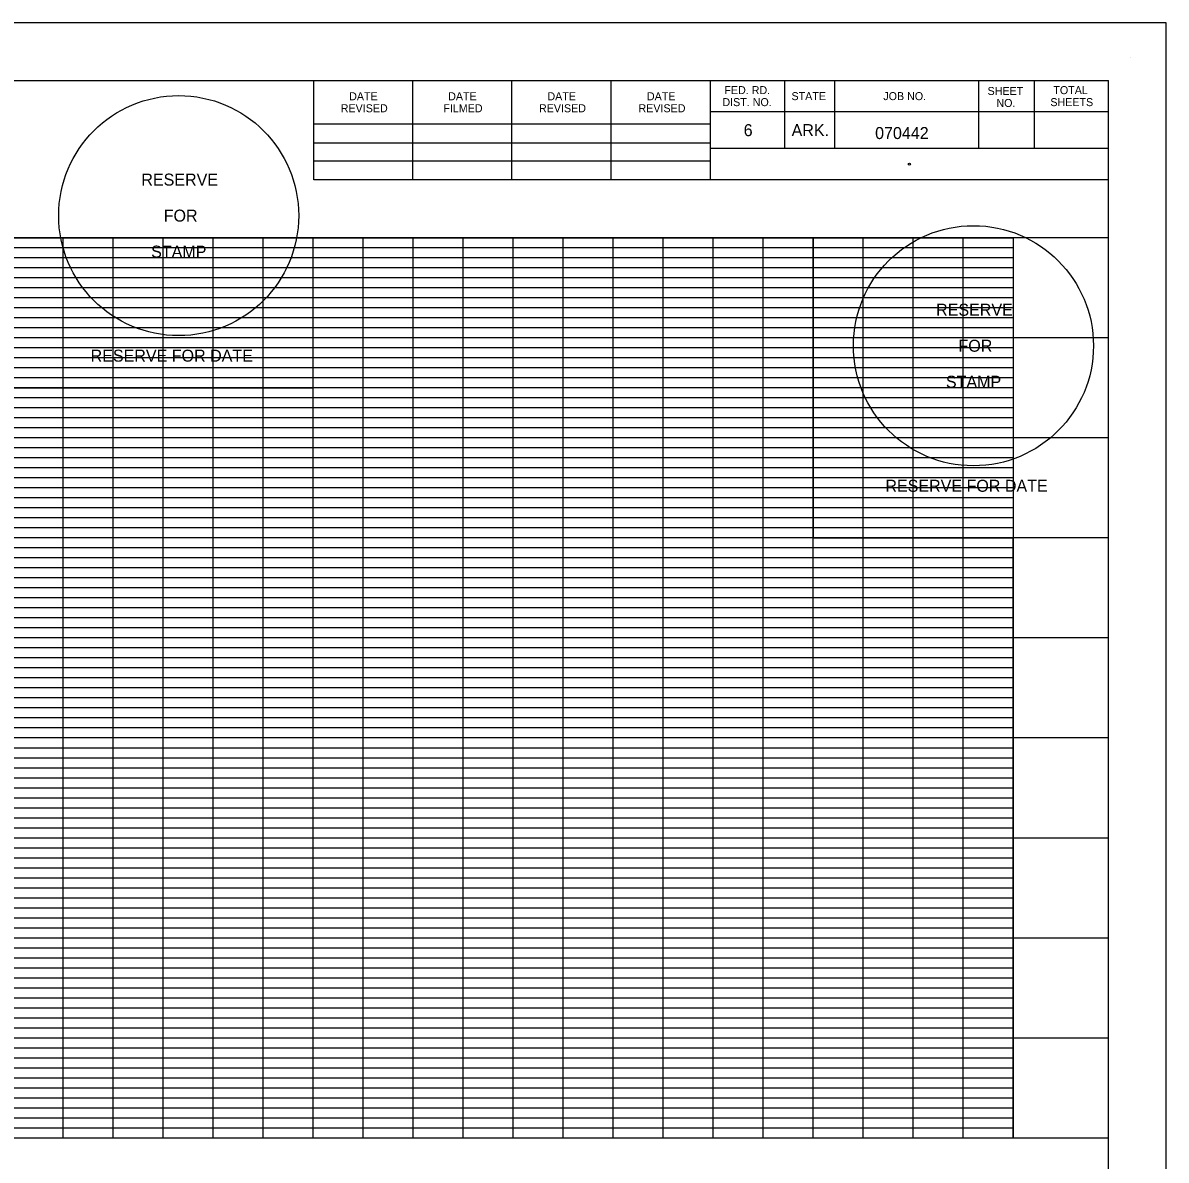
# Model space of a CAD drawing. Extents: x 1446988 to 1448688, y 2058337 to 2059437.
import ezdxf

# ---------------------------------------------------------------- set-up
doc = ezdxf.new("R2010")
doc.units = 0
for name, color, linetype in [('1', 7, 'Continuous'), ('G-ANNO-TEXT', 7, 'Continuous'), ('G-Border-Sheet', 7, 'Continuous'), ('G-Grid-Border-1', 7, 'Continuous'), ('G-Grid-Border-2', 7, 'Continuous'), ('G-Grid-Major-1', 7, 'Continuous'), ('G-Grid-Major-2', 7, 'Continuous'), ('G-Grid-Minor-1', 7, 'Continuous'), ('G-Grid-Minor-2', 7, 'Continuous'), ('G-No Plot-Anchor', 7, 'Continuous'), ('G-No Plot-Stamp-1', 7, 'Continuous'), ('G-No Plot-Stamp-2', 7, 'Continuous'), ('G-Table-Major', 7, 'Continuous'), ('G-Table-Minor', 7, 'Continuous')]:
    doc.layers.add(name, color=color, linetype=linetype)

msp = doc.modelspace()

# ---------------------------------------------------------------- linework, layer by layer
at = {"layer": '1'}
msp.add_lwpolyline([(1448688.42, 2059436.53), (1446988.42, 2059436.53), (1446988.42, 2058336.53), (1448688.42, 2058336.53)], close=True, dxfattribs=at)
at = {"layer": 'G-ANNO-TEXT'}
msp.add_line((1448670.52, 2059419.23), (1448670.52, 2059419.23), dxfattribs=at)
at = {"layer": 'G-Border-Sheet'}
for p in [(1447064.22, 2059407.69), (1448659.58, 2058365.37)]:
    msp.add_line(p, (1448659.58, 2059407.69), dxfattribs=at)
at = {"layer": 'G-Grid-Border-1'}
for p, q in [((1448508.75, 2059329.09), (1447064.22, 2059329.09)), ((1448659.58, 2058879.09), (1447064.22, 2058879.09))]:
    msp.add_line(p, q, dxfattribs=at)
msp.add_lwpolyline([(1447111.9, 2059329.09), (1448511.9, 2059329.09), (1448511.9, 2059179.09), (1448611.9, 2059179.09), (1448611.9, 2058879.09), (1447111.9, 2058879.09)], close=True, dxfattribs=at)
at = {"layer": 'G-Grid-Border-2'}
for p, q in [((1448261.9, 2059254.09), (1448261.9, 2059329.09)), ((1448659.58, 2059329.09), (1448261.9, 2059329.09)), ((1448261.9, 2059254.09), (1448261.9, 2059329.09)), ((1448111.9, 2059254.09), (1448261.9, 2059254.09)), ((1448111.9, 2059254.09), (1448261.9, 2059254.09)), ((1448611.9, 2058879.09), (1448611.9, 2059179.09)), ((1448659.58, 2058879.09), (1447064.22, 2058879.09))]:
    msp.add_line(p, q, dxfattribs=at)
msp.add_lwpolyline([(1447111.9, 2059329.09), (1448111.9, 2059329.09), (1448111.9, 2059254.09), (1448261.9, 2059254.09), (1448261.9, 2059329.09), (1448611.9, 2059329.09), (1448611.9, 2058879.09), (1447111.9, 2058879.09)], close=True, dxfattribs=at)
at = {"layer": 'G-Grid-Major-1'}
for p, q in [((1448161.9, 2058879.09), (1448161.9, 2059329.09)), ((1448211.9, 2058879.09), (1448211.9, 2059329.09)), ((1448261.9, 2058879.09), (1448261.9, 2059329.09)), ((1448311.9, 2058879.09), (1448311.9, 2059329.09)), ((1448361.9, 2058879.09), (1448361.9, 2059329.09)), ((1448411.9, 2058879.09), (1448411.9, 2059329.09)), ((1448461.9, 2058879.09), (1448461.9, 2059329.09)), ((1448511.9, 2058879.09), (1448511.9, 2059329.09)), ((1448511.9, 2059279.09), (1447064.22, 2059279.09)), ((1448511.9, 2059229.09), (1447064.22, 2059229.09)), ((1448659.58, 2059179.09), (1447064.22, 2059179.09)), ((1448561.9, 2058879.09), (1448561.9, 2059179.09)), ((1448659.58, 2059129.09), (1447064.22, 2059129.09)), ((1448659.58, 2059079.09), (1447064.22, 2059079.09)), ((1448659.58, 2059029.09), (1447064.22, 2059029.09)), ((1448659.58, 2058979.09), (1447064.22, 2058979.09)), ((1448659.58, 2058929.09), (1447064.22, 2058929.09))]:
    msp.add_line(p, q, dxfattribs=at)
at = {"layer": 'G-Grid-Major-2'}
for p, q in [((1448261.9, 2058879.09), (1448261.9, 2059329.09)), ((1448311.9, 2058879.09), (1448311.9, 2059329.09)), ((1448361.9, 2058879.09), (1448361.9, 2059329.09)), ((1448411.9, 2058879.09), (1448411.9, 2059329.09)), ((1448461.9, 2058879.09), (1448461.9, 2059329.09)), ((1448511.9, 2058879.09), (1448511.9, 2059329.09)), ((1448561.9, 2058879.09), (1448561.9, 2059329.09)), ((1448659.58, 2059279.09), (1448261.9, 2059279.09)), ((1448161.9, 2058879.09), (1448161.9, 2059254.09)), ((1448211.9, 2058879.09), (1448211.9, 2059254.09)), ((1448659.58, 2059229.09), (1447064.22, 2059229.09)), ((1448659.58, 2059179.09), (1447064.22, 2059179.09)), ((1448659.58, 2059129.09), (1447064.22, 2059129.09)), ((1448659.58, 2059079.09), (1447064.22, 2059079.09)), ((1448659.58, 2059029.09), (1447064.22, 2059029.09)), ((1448659.58, 2058979.09), (1447064.22, 2058979.09)), ((1448659.58, 2058929.09), (1447064.22, 2058929.09))]:
    msp.add_line(p, q, dxfattribs=at)
at = {"layer": 'G-Grid-Minor-1'}
for p, q in [((1448136.9, 2058879.09), (1448136.9, 2059329.09)), ((1448186.9, 2058879.09), (1448186.9, 2059329.09)), ((1448236.9, 2058879.09), (1448236.9, 2059329.09)), ((1448286.9, 2058879.09), (1448286.9, 2059329.09)), ((1448336.9, 2058879.09), (1448336.9, 2059329.09)), ((1448386.9, 2058879.09), (1448386.9, 2059329.09)), ((1448436.9, 2058879.09), (1448436.9, 2059329.09)), ((1448486.9, 2058879.09), (1448486.9, 2059329.09)), ((1448511.9, 2059324.09), (1447111.9, 2059324.09)), ((1448511.9, 2059319.09), (1447111.9, 2059319.09)), ((1448511.9, 2059314.09), (1447111.9, 2059314.09)), ((1448511.9, 2059309.09), (1447111.9, 2059309.09)), ((1448511.9, 2059304.09), (1447111.9, 2059304.09)), ((1448511.9, 2059299.09), (1447111.9, 2059299.09)), ((1448511.9, 2059294.09), (1447111.9, 2059294.09)), ((1448511.9, 2059289.09), (1447111.9, 2059289.09)), ((1448511.9, 2059284.09), (1447111.9, 2059284.09)), ((1448511.9, 2059274.09), (1447111.9, 2059274.09)), ((1448511.9, 2059269.09), (1447111.9, 2059269.09)), ((1448511.9, 2059264.09), (1447111.9, 2059264.09)), ((1448511.9, 2059259.09), (1447111.9, 2059259.09)), ((1448511.9, 2059254.09), (1447111.9, 2059254.09)), ((1448511.9, 2059249.09), (1447111.9, 2059249.09)), ((1448511.9, 2059244.09), (1447111.9, 2059244.09)), ((1448511.9, 2059239.09), (1447111.9, 2059239.09)), ((1448511.9, 2059234.09), (1447111.9, 2059234.09)), ((1448511.9, 2059224.09), (1447111.9, 2059224.09)), ((1448511.9, 2059219.09), (1447111.9, 2059219.09)), ((1448511.9, 2059214.09), (1447111.9, 2059214.09)), ((1448511.9, 2059209.09), (1447111.9, 2059209.09)), ((1448511.9, 2059204.09), (1447111.9, 2059204.09)), ((1448511.9, 2059199.09), (1447111.9, 2059199.09)), ((1448511.9, 2059194.09), (1447111.9, 2059194.09)), ((1448511.9, 2059189.09), (1447111.9, 2059189.09)), ((1448511.9, 2059184.09), (1447111.9, 2059184.09)), ((1448536.9, 2058879.09), (1448536.9, 2059179.09)), ((1448586.9, 2058879.09), (1448586.9, 2059179.09)), ((1448611.9, 2059174.09), (1447111.9, 2059174.09)), ((1448611.9, 2059169.09), (1447111.9, 2059169.09)), ((1448611.9, 2059164.09), (1447111.9, 2059164.09)), ((1448611.9, 2059159.09), (1447111.9, 2059159.09)), ((1448611.9, 2059154.09), (1447111.9, 2059154.09)), ((1448611.9, 2059149.09), (1447111.9, 2059149.09)), ((1448611.9, 2059144.09), (1447111.9, 2059144.09)), ((1448611.9, 2059139.09), (1447111.9, 2059139.09)), ((1448611.9, 2059134.09), (1447111.9, 2059134.09)), ((1448611.9, 2059124.09), (1447111.9, 2059124.09)), ((1448611.9, 2059119.09), (1447111.9, 2059119.09)), ((1448611.9, 2059114.09), (1447111.9, 2059114.09)), ((1448611.9, 2059109.09), (1447111.9, 2059109.09)), ((1448611.9, 2059104.09), (1447111.9, 2059104.09)), ((1448611.9, 2059099.09), (1447111.9, 2059099.09)), ((1448611.9, 2059094.09), (1447111.9, 2059094.09)), ((1448611.9, 2059089.09), (1447111.9, 2059089.09)), ((1448611.9, 2059084.09), (1447111.9, 2059084.09)), ((1448611.9, 2059074.09), (1447111.9, 2059074.09)), ((1448611.9, 2059069.09), (1447111.9, 2059069.09)), ((1448611.9, 2059064.09), (1447111.9, 2059064.09)), ((1448611.9, 2059059.09), (1447111.9, 2059059.09)), ((1448611.9, 2059054.09), (1447111.9, 2059054.09)), ((1448611.9, 2059049.09), (1447111.9, 2059049.09)), ((1448611.9, 2059044.09), (1447111.9, 2059044.09)), ((1448611.9, 2059039.09), (1447111.9, 2059039.09)), ((1448611.9, 2059034.09), (1447111.9, 2059034.09)), ((1448611.9, 2059024.09), (1447111.9, 2059024.09)), ((1448611.9, 2059019.09), (1447111.9, 2059019.09)), ((1448611.9, 2059014.09), (1447111.9, 2059014.09)), ((1448611.9, 2059009.09), (1447111.9, 2059009.09)), ((1448611.9, 2059004.09), (1447111.9, 2059004.09)), ((1448611.9, 2058999.09), (1447111.9, 2058999.09)), ((1448611.9, 2058994.09), (1447111.9, 2058994.09)), ((1448611.9, 2058989.09), (1447111.9, 2058989.09)), ((1448611.9, 2058984.09), (1447111.9, 2058984.09)), ((1448611.9, 2058974.09), (1447111.9, 2058974.09)), ((1448611.9, 2058969.09), (1447111.9, 2058969.09)), ((1448611.9, 2058964.09), (1447111.9, 2058964.09)), ((1448611.9, 2058959.09), (1447111.9, 2058959.09)), ((1448611.9, 2058954.09), (1447111.9, 2058954.09)), ((1448611.9, 2058949.09), (1447111.9, 2058949.09)), ((1448611.9, 2058944.09), (1447111.9, 2058944.09)), ((1448611.9, 2058939.09), (1447111.9, 2058939.09)), ((1448611.9, 2058934.09), (1447111.9, 2058934.09)), ((1448611.9, 2058924.09), (1447111.9, 2058924.09)), ((1448611.9, 2058919.09), (1447111.9, 2058919.09)), ((1448611.9, 2058914.09), (1447111.9, 2058914.09)), ((1448611.9, 2058909.09), (1447111.9, 2058909.09)), ((1448611.9, 2058904.09), (1447111.9, 2058904.09)), ((1448611.9, 2058899.09), (1447111.9, 2058899.09)), ((1448611.9, 2058894.09), (1447111.9, 2058894.09)), ((1448611.9, 2058889.09), (1447111.9, 2058889.09)), ((1448611.9, 2058884.09), (1447111.9, 2058884.09))]:
    msp.add_line(p, q, dxfattribs=at)
msp.add_lwpolyline([(1448611.9, 2059179.09), (1448611.9, 2058879.09), (1447111.9, 2058879.09), (1447111.9, 2059329.09)], dxfattribs=at)
at = {"layer": 'G-Grid-Minor-2'}
for p, q in [((1448286.9, 2058879.09), (1448286.9, 2059329.09)), ((1448336.9, 2058879.09), (1448336.9, 2059329.09)), ((1448386.9, 2058879.09), (1448386.9, 2059329.09)), ((1448436.9, 2058879.09), (1448436.9, 2059329.09)), ((1448486.9, 2058879.09), (1448486.9, 2059329.09)), ((1448536.9, 2058879.09), (1448536.9, 2059329.09)), ((1448586.9, 2058879.09), (1448586.9, 2059329.09)), ((1448611.9, 2059324.09), (1448261.9, 2059324.09)), ((1448611.9, 2059319.09), (1448261.9, 2059319.09)), ((1448611.9, 2059314.09), (1448261.9, 2059314.09)), ((1448611.9, 2059309.09), (1448261.9, 2059309.09)), ((1448611.9, 2059304.09), (1448261.9, 2059304.09)), ((1448611.9, 2059299.09), (1448261.9, 2059299.09)), ((1448611.9, 2059294.09), (1448261.9, 2059294.09)), ((1448611.9, 2059289.09), (1448261.9, 2059289.09)), ((1448611.9, 2059284.09), (1448261.9, 2059284.09)), ((1448611.9, 2059274.09), (1448261.9, 2059274.09)), ((1448611.9, 2059269.09), (1448261.9, 2059269.09)), ((1448611.9, 2059264.09), (1448261.9, 2059264.09)), ((1448611.9, 2059259.09), (1448261.9, 2059259.09)), ((1448611.9, 2059254.09), (1447111.9, 2059254.09)), ((1448136.9, 2058879.09), (1448136.9, 2059254.09)), ((1448186.9, 2058879.09), (1448186.9, 2059254.09)), ((1448236.9, 2058879.09), (1448236.9, 2059254.09)), ((1448611.9, 2059249.09), (1447111.9, 2059249.09)), ((1448611.9, 2059244.09), (1447111.9, 2059244.09)), ((1448611.9, 2059239.09), (1447111.9, 2059239.09)), ((1448611.9, 2059234.09), (1447111.9, 2059234.09)), ((1448611.9, 2059224.09), (1447111.9, 2059224.09)), ((1448611.9, 2059219.09), (1447111.9, 2059219.09)), ((1448611.9, 2059214.09), (1447111.9, 2059214.09)), ((1448611.9, 2059209.09), (1447111.9, 2059209.09)), ((1448611.9, 2059204.09), (1447111.9, 2059204.09)), ((1448611.9, 2059199.09), (1447111.9, 2059199.09)), ((1448611.9, 2059194.09), (1447111.9, 2059194.09)), ((1448611.9, 2059189.09), (1447111.9, 2059189.09)), ((1448611.9, 2059184.09), (1447111.9, 2059184.09)), ((1448611.9, 2059174.09), (1447111.9, 2059174.09)), ((1448611.9, 2059169.09), (1447111.9, 2059169.09)), ((1448611.9, 2059164.09), (1447111.9, 2059164.09)), ((1448611.9, 2059159.09), (1447111.9, 2059159.09)), ((1448611.9, 2059154.09), (1447111.9, 2059154.09)), ((1448611.9, 2059149.09), (1447111.9, 2059149.09)), ((1448611.9, 2059144.09), (1447111.9, 2059144.09)), ((1448611.9, 2059139.09), (1447111.9, 2059139.09)), ((1448611.9, 2059134.09), (1447111.9, 2059134.09)), ((1448611.9, 2059124.09), (1447111.9, 2059124.09)), ((1448611.9, 2059119.09), (1447111.9, 2059119.09)), ((1448611.9, 2059114.09), (1447111.9, 2059114.09)), ((1448611.9, 2059109.09), (1447111.9, 2059109.09)), ((1448611.9, 2059104.09), (1447111.9, 2059104.09)), ((1448611.9, 2059099.09), (1447111.9, 2059099.09)), ((1448611.9, 2059094.09), (1447111.9, 2059094.09)), ((1448611.9, 2059089.09), (1447111.9, 2059089.09)), ((1448611.9, 2059084.09), (1447111.9, 2059084.09)), ((1448611.9, 2059074.09), (1447111.9, 2059074.09)), ((1448611.9, 2059069.09), (1447111.9, 2059069.09)), ((1448611.9, 2059064.09), (1447111.9, 2059064.09)), ((1448611.9, 2059059.09), (1447111.9, 2059059.09)), ((1448611.9, 2059054.09), (1447111.9, 2059054.09)), ((1448611.9, 2059049.09), (1447111.9, 2059049.09)), ((1448611.9, 2059044.09), (1447111.9, 2059044.09)), ((1448611.9, 2059039.09), (1447111.9, 2059039.09)), ((1448611.9, 2059034.09), (1447111.9, 2059034.09)), ((1448611.9, 2059024.09), (1447111.9, 2059024.09)), ((1448611.9, 2059019.09), (1447111.9, 2059019.09)), ((1448611.9, 2059014.09), (1447111.9, 2059014.09)), ((1448611.9, 2059009.09), (1447111.9, 2059009.09)), ((1448611.9, 2059004.09), (1447111.9, 2059004.09)), ((1448611.9, 2058999.09), (1447111.9, 2058999.09)), ((1448611.9, 2058994.09), (1447111.9, 2058994.09)), ((1448611.9, 2058989.09), (1447111.9, 2058989.09)), ((1448611.9, 2058984.09), (1447111.9, 2058984.09)), ((1448611.9, 2058974.09), (1447111.9, 2058974.09)), ((1448611.9, 2058969.09), (1447111.9, 2058969.09)), ((1448611.9, 2058964.09), (1447111.9, 2058964.09)), ((1448611.9, 2058959.09), (1447111.9, 2058959.09)), ((1448611.9, 2058954.09), (1447111.9, 2058954.09)), ((1448611.9, 2058949.09), (1447111.9, 2058949.09)), ((1448611.9, 2058944.09), (1447111.9, 2058944.09)), ((1448611.9, 2058939.09), (1447111.9, 2058939.09)), ((1448611.9, 2058934.09), (1447111.9, 2058934.09)), ((1448611.9, 2058924.09), (1447111.9, 2058924.09)), ((1448611.9, 2058919.09), (1447111.9, 2058919.09)), ((1448611.9, 2058914.09), (1447111.9, 2058914.09)), ((1448611.9, 2058909.09), (1447111.9, 2058909.09)), ((1448611.9, 2058904.09), (1447111.9, 2058904.09)), ((1448611.9, 2058899.09), (1447111.9, 2058899.09)), ((1448611.9, 2058894.09), (1447111.9, 2058894.09)), ((1448611.9, 2058889.09), (1447111.9, 2058889.09)), ((1448611.9, 2058884.09), (1447111.9, 2058884.09))]:
    msp.add_line(p, q, dxfattribs=at)
msp.add_lwpolyline([(1448611.9, 2059179.09), (1448611.9, 2058879.09), (1447111.9, 2058879.09), (1447111.9, 2059329.09)], dxfattribs=at)
at = {"layer": 'G-No Plot-Anchor'}
msp.add_circle((1448560.03, 2059365.9), 0.5, dxfattribs=at)
at = {"layer": 'G-No Plot-Stamp-1'}
msp.add_circle((1448592.08, 2059275.15), 60, dxfattribs=at)
at = {"layer": 'G-No Plot-Stamp-2'}
msp.add_circle((1448194.73, 2059340.19), 60, dxfattribs=at)
at = {"layer": 'G-Table-Major'}
for p, q in [((1448262.23, 2059358.15), (1448262.23, 2059407.69)), ((1448361.23, 2059358.22), (1448361.23, 2059407.69)), ((1448460.48, 2059407.69), (1448460.48, 2059358.15)), ((1448262.23, 2059386), (1448460.48, 2059386)), ((1448659.58, 2059358.15), (1448262.23, 2059358.15))]:
    msp.add_line(p, q, dxfattribs=at)
at = {"layer": 'G-Table-Minor'}
for p, q in [((1448311.73, 2059358.15), (1448311.73, 2059407.69)), ((1448410.98, 2059358.18), (1448410.98, 2059407.69)), ((1448497.68, 2059407.69), (1448497.68, 2059373.7)), ((1448522.53, 2059407.69), (1448522.53, 2059373.7)), ((1448594.58, 2059407.69), (1448594.58, 2059373.7)), ((1448622.38, 2059407.69), (1448622.38, 2059373.7)), ((1448659.58, 2059392.15), (1448460.48, 2059392.15)), ((1448659.58, 2059393.09), (1448659.58, 2059393.09)), ((1448262.23, 2059376.65), (1448460.48, 2059376.65)), ((1448659.58, 2059373.7), (1448460.48, 2059373.7)), ((1448262.23, 2059367.5), (1448460.48, 2059367.5))]:
    msp.add_line(p, q, dxfattribs=at)

# ---------------------------------------------------------------- texts
at = {"layer": 'G-ANNO-TEXT'}
for s, height, p in [('DATE', 4, (1448279.95, 2059397.85)), ('DATE', 4, (1448329.45, 2059397.85)), ('DATE', 4, (1448379.08, 2059397.85)), ('DATE', 4, (1448428.83, 2059397.85)), ('FED. RD.', 4, (1448467.55, 2059400.92)), ('STATE', 4, (1448501.12, 2059397.92)), ('JOB NO.', 4, (1448547.02, 2059397.92)), ('SHEET', 4, (1448599.14, 2059400.5)), ('TOTAL', 4, (1448632.03, 2059400.92)), ('REVISED', 4, (1448275.75, 2059391.85)), ('FILMED', 4, (1448327.04, 2059391.85)), ('REVISED', 4, (1448374.87, 2059391.85)), ('REVISED', 4, (1448424.62, 2059391.85)), ('DIST. NO.', 4, (1448466.57, 2059394.92)), ('NO.', 4, (1448603.56, 2059394.5)), ('SHEETS', 4, (1448630.52, 2059394.92)), ('6', 6, (1448477.21, 2059379.92)), ('ARK.', 6, (1448501.17, 2059379.92)), ('070442', 6, (1448542.91, 2059378.47))]:
    msp.add_text(s, height=height, dxfattribs=at).set_placement(p)
at = {"layer": 'G-No Plot-Stamp-1'}
for s, p in [('RESERVE', (1448573.42, 2059290.15)), ('FOR ', (1448584.59, 2059272.15)), ('STAMP', (1448578.31, 2059254.15)), ('RESERVE FOR DATE', (1448548.05, 2059202.15))]:
    msp.add_text(s, height=6, dxfattribs=at).set_placement(p)
at = {"layer": 'G-No Plot-Stamp-2'}
for s, p in [('RESERVE', (1448176.06, 2059355.19)), ('FOR ', (1448187.24, 2059337.19)), ('STAMP', (1448180.95, 2059319.19)), ('RESERVE FOR DATE', (1448150.69, 2059267.19)), ('RESERVE FOR DATE', (1448150.69, 2059267.19))]:
    msp.add_text(s, height=6, dxfattribs=at).set_placement(p)

doc.saveas('drawing.dxf')
